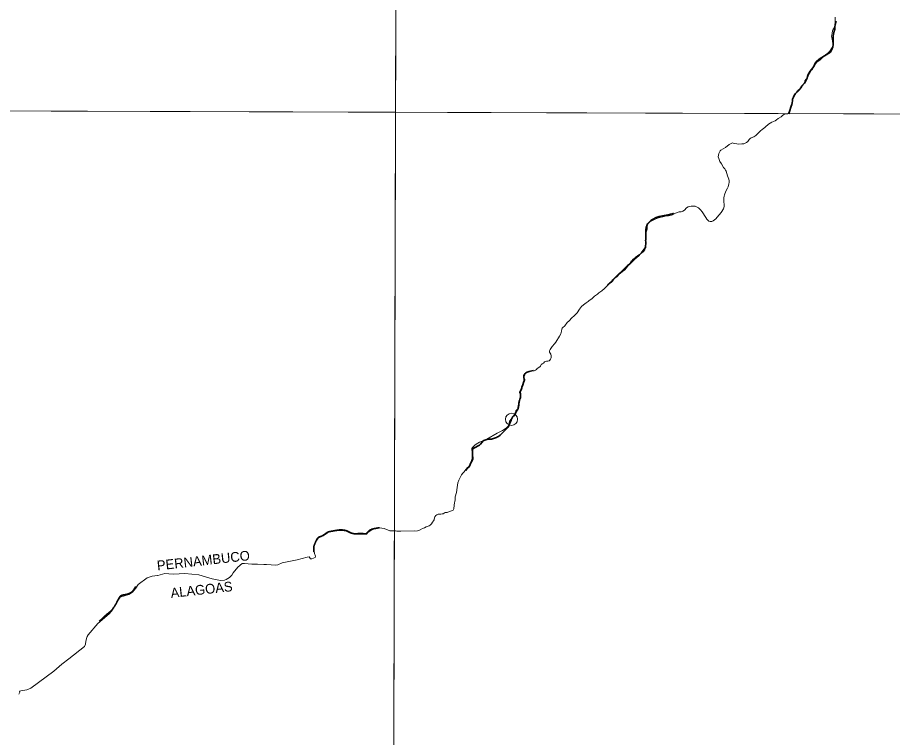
# Model space of a CAD drawing. Extents: x -1643653 to 4543381, y 1624270 to 13878484.
# Drawn here: x 582541 to 589726, y 8915895 to 8921805 of the extents above; entities that cross this region are included whole.
import ezdxf
from ezdxf.enums import TextEntityAlignment as Align

# ---------------------------------------------------------------- set-up
doc = ezdxf.new("R2010")
doc.units = 0
doc.header["$LTSCALE"] = 200
doc.header["$PDMODE"] = 32
doc.header["$PDSIZE"] = 100
doc.linetypes.add('LONG_DASH_SHORT_DASH', pattern=[9.9, 6, -1.2, 1.5, -1.2])
doc.layers.add('6', color=7, linetype='Continuous', lineweight=13)
doc.layers.add('60', color=7, linetype='Continuous', lineweight=13)

msp = doc.modelspace()

# ---------------------------------------------------------------- linework, layer by layer
at = {"layer": '6', "linetype": 'LONG_DASH_SHORT_DASH', "lineweight": 35}
msp.add_line((585799, 8917597.9), (585799.3, 8917597.8), dxfattribs=at)
at = {"layer": '6'}
for points in [[(585656.3, 8924738.8), (585614.8, 8909969.8), (585573.6, 8896026.7)], [(589006.9, 8921286.1), (589017.7, 8921298.2), (589025.9, 8921311.4), (589032.3, 8921323.1), (589038.7, 8921335.9), (589044.8, 8921346.8), (589061.1, 8921374.5), (589062.1, 8921375.7), (589065.5, 8921376.8), (589066.3, 8921377.4), (589067.9, 8921382.3), (589080.2, 8921406.4), (589088.1, 8921416.9), (589095.6, 8921428.2), (589103, 8921436.9), (589114.8, 8921446.2), (589127.9, 8921454.3), (589138.6, 8921462.4), (589156.6, 8921481.7), (589166.2, 8921490.8), (589178.1, 8921500.6), (589191.4, 8921510), (589200.1, 8921518.9), (589210.1, 8921529.4), (589229.5, 8921558.3), (589234.5, 8921575.8), (589235.7, 8921589), (589233, 8921614.5), (589230.5, 8921626.8), (589227.1, 8921641), (589225.9, 8921651.4), (589226.5, 8921662.7), (589229.7, 8921674.9), (589234.2, 8921697.9), (589238.6, 8921709.2), (589245.8, 8921721.4), (589253.2, 8921743.4), (589255.8, 8921757.4), (589255.8, 8921769.2), (589254.4, 8921783), (589254.5, 8921808.2)], [(588894.1, 8921078.3), (588899.6, 8921098.8), (588904.2, 8921126.1), (588914.3, 8921152.8), (588920.1, 8921165.7), (588925.5, 8921176.6), (588933.3, 8921185.3), (588950, 8921200.7), (588958.1, 8921209.6), (588965.2, 8921218.7), (588971.4, 8921228.1), (588977.2, 8921237.7), (588983.2, 8921246), (588992.1, 8921255.2), (589001.3, 8921265.6), (589006.1, 8921273.9), (589006.9, 8921286.1)], [(574684.9, 8921064.7), (596639.8, 8920989.8), (607636.3, 8920937.2), (626625.7, 8920820.5)], [(588866, 8921014.8), (588889.6, 8921061.5), (588894.1, 8921078.3)], [(588655.6, 8920885.9), (588677.4, 8920901.9), (588686.9, 8920909.9), (588701.1, 8920923.5), (588708.3, 8920929.1), (588735.8, 8920945.1), (588763.3, 8920958.1), (588772.3, 8920964.5), (588787.3, 8920977.1), (588811.4, 8920991.1), (588822.9, 8921000.3), (588834.6, 8921008.1), (588849.2, 8921013.6), (588866, 8921014.8)], [(588133.1, 8920242.8), (588149.7, 8920226.2), (588162.1, 8920210.6), (588192.2, 8920163.2), (588200.8, 8920151.2), (588210.3, 8920141), (588218.2, 8920134.2), (588229.5, 8920131.2), (588239.4, 8920130.6), (588242.6, 8920131.2), (588252.2, 8920136.2), (588263.6, 8920144.6), (588274.1, 8920153.8), (588286.8, 8920167.4), (588317.7, 8920204.6), (588338.9, 8920234.8), (588341.5, 8920240.4), (588344.1, 8920258), (588343.1, 8920273.4), (588340.8, 8920288.6), (588341.3, 8920325.6), (588343.4, 8920340), (588346, 8920349.4), (588356.8, 8920379.2), (588371.2, 8920405), (588375.2, 8920414.2), (588383.2, 8920440), (588384.8, 8920451.4), (588384.9, 8920464.6), (588382.6, 8920479), (588371.7, 8920504.6), (588359.6, 8920544.4), (588355, 8920553.2), (588348.1, 8920563.6), (588339.4, 8920574.6), (588322.3, 8920605), (588308.9, 8920623.2), (588298.6, 8920647.4), (588295.4, 8920660.6), (588295.9, 8920674.4), (588299.2, 8920688.8), (588303.9, 8920701), (588310.3, 8920711), (588316.9, 8920717), (588354.3, 8920738), (588383.7, 8920762), (588395.1, 8920768.6), (588407.3, 8920773.8), (588413, 8920775.2), (588418.4, 8920774.8), (588460.6, 8920766.8), (588487.3, 8920768.8), (588503.7, 8920768.2), (588522.2, 8920775.8), (588526.8, 8920778.8), (588537.4, 8920788.2), (588548.5, 8920803.2), (588555.8, 8920810.9), (588564.9, 8920816.8), (588587.7, 8920826.9), (588603.8, 8920836.1), (588610.7, 8920843.9), (588624, 8920855.9), (588641.9, 8920874.5), (588655.5, 8920886.1)], [(587691.5, 8919899.2), (587695.6, 8919912), (587699.2, 8919964.2), (587697.5, 8919992.4), (587697.6, 8920004.6), (587700.8, 8920020), (587703.5, 8920044.2), (587710.4, 8920069), (587712.5, 8920094.4), (587714.5, 8920104.2), (587717.9, 8920111), (587723, 8920118), (587730.8, 8920125.6), (587748.4, 8920136.4), (587759.7, 8920142.4), (587778.2, 8920150.6), (587804, 8920160), (587849.8, 8920172.2), (587870.3, 8920176.6), (587885.6, 8920178.2), (587910.3, 8920183.8), (587917, 8920186.6), (587930.3, 8920193.8), (587965.5, 8920207.4), (587974.1, 8920208.8), (587989.3, 8920209.2), (587999.8, 8920211.8), (588005.2, 8920214.8), (588016.8, 8920224), (588035.3, 8920241.8), (588046.8, 8920250.6), (588055.4, 8920254.4), (588071.6, 8920256.6), (588094, 8920257.2), (588104.9, 8920255.8), (588121.9, 8920249.6), (588133.1, 8920242.8)], [(586916.9, 8918999.4), (586921.8, 8919011.7), (586923.2, 8919017.8), (586923.8, 8919027.8), (586919.9, 8919040.7), (586909.9, 8919057.1), (586909, 8919064.2), (586909.4, 8919069.7), (586914.4, 8919080.4), (586932.4, 8919104.2), (586949.8, 8919125.1), (586961.5, 8919140.2), (586992.8, 8919190.2), (587002.7, 8919209.4), (587006.2, 8919218.4), (587008.9, 8919230.4), (587010.4, 8919247.4), (587012.9, 8919254.6), (587016, 8919258.6), (587035, 8919274.8), (587055.6, 8919302.4), (587072, 8919316.4), (587094, 8919340.4), (587112.3, 8919355.2), (587126.1, 8919368.8), (587137.1, 8919382), (587155.1, 8919411), (587172.6, 8919433.8), (587187.4, 8919446.2), (587211.4, 8919462), (587226.2, 8919474.8), (587234.8, 8919481.4), (587256, 8919495), (587279.1, 8919516.8), (587302.2, 8919534.6), (587313.3, 8919545), (587338.1, 8919562.4), (587360.9, 8919581.2), (587383.5, 8919602), (587399.3, 8919618), (587418.7, 8919633.8), (587431.5, 8919646.8), (587438.1, 8919658.2), (587442.8, 8919664), (587447.3, 8919667.4), (587454, 8919670.8), (587465.3, 8919679.2), (587481.8, 8919698.6), (587488.5, 8919705), (587509.1, 8919720), (587523.9, 8919732.2), (587542.4, 8919750.6), (587556.5, 8919769.4), (587562.2, 8919775.8), (587583.5, 8919793.8), (587602, 8919814.2), (587611.3, 8919821.8), (587622.8, 8919832.8), (587643.4, 8919849.8), (587655.9, 8919864), (587663.9, 8919871.6), (587678.6, 8919882), (587683.7, 8919887), (587691.5, 8919899.2), (587691.5, 8919899.2)], [(586679.6, 8918760.5), (586680.3, 8918772.5), (586692.5, 8918786.5), (586696.8, 8918798.9), (586696.9, 8918809.3), (586697.7, 8918812.7), (586699.3, 8918815.3), (586704.2, 8918820.1), (586707.7, 8918826.9), (586707.4, 8918834.5), (586702.6, 8918847.7), (586701.8, 8918857.5), (586703.1, 8918864.1), (586709.7, 8918881.3), (586721, 8918893.5), (586725.9, 8918895.7), (586766.1, 8918904.9), (586782.2, 8918905.1), (586794.3, 8918909.1), (586801.8, 8918914.7), (586808.8, 8918923.3), (586813, 8918927.3), (586824.3, 8918933.9), (586830.1, 8918938.5), (586834.8, 8918944.1), (586841.9, 8918955.9), (586845.8, 8918960.3), (586848.8, 8918962.4), (586859.7, 8918966.8), (586863.7, 8918970.4), (586869.3, 8918977.4), (586877.2, 8918981.7), (586883.6, 8918984.1), (586895.7, 8918985.2), (586905.7, 8918987.4), (586911.9, 8918992.7), (586916.9, 8918999.4)], [(586136.8, 8917879.9), (586143.9, 8917898.3), (586146.5, 8917907.1), (586150.7, 8917947.5), (586156.3, 8917986.5), (586166.2, 8918006.3), (586175.4, 8918028.7), (586186.6, 8918050.1), (586197.8, 8918063.5), (586206.1, 8918071.9), (586225, 8918098.7), (586234.8, 8918109.9), (586249.5, 8918120.5), (586256.8, 8918127.7), (586261.3, 8918135.7), (586262.8, 8918149.5), (586276.3, 8918165.5), (586281.8, 8918176.7), (586282.8, 8918182.3), (586282.8, 8918191.1), (586279.2, 8918209.5), (586279.1, 8918219.3), (586275.1, 8918241.3), (586270.8, 8918255.1), (586270.6, 8918261.3), (586271.5, 8918267.7), (586278.2, 8918274.1), (586295.8, 8918294.9), (586307.4, 8918303.7), (586335.1, 8918320.1), (586377.8, 8918336.7), (586395.1, 8918344.9), (586480.1, 8918393.5), (586505.7, 8918406.7), (586524.1, 8918414.9), (586554, 8918433.1), (586568.4, 8918447.3), (586570.6, 8918451.1), (586575.7, 8918463.9), (586578.3, 8918475.3), (586579.7, 8918491.9), (586595.5, 8918507.3), (586602.8, 8918522.3), (586607.5, 8918529.5), (586619.7, 8918540.1), (586627.3, 8918548.9), (586630.1, 8918555.5), (586632.3, 8918569.5), (586634.1, 8918575.1), (586636.7, 8918579.5), (586645.9, 8918589.1), (586648.8, 8918594.9), (586650.6, 8918604.3), (586653.5, 8918631.7), (586658.1, 8918644.7), (586665.3, 8918659.3), (586672.6, 8918692.7), (586672.6, 8918710.3), (586671.1, 8918715.7), (586665.9, 8918726.3), (586666, 8918731.5), (586668, 8918736.7), (586678.5, 8918755.1), (586678.5, 8918755.1), (586679.6, 8918760.5)], [(585824.4, 8917592.5), (585835.6, 8917593.5), (585848.5, 8917598.3), (585866.6, 8917609.5), (585883, 8917614.7), (585896.8, 8917622.9), (585921, 8917633.3), (585928.7, 8917638.5), (585940.3, 8917649.7), (585947.5, 8917662.7), (585957.1, 8917673.5), (585961.2, 8917682.5), (585965.9, 8917699.7), (585968.9, 8917706.9), (585976, 8917717.1), (585984.1, 8917723.9), (585988.6, 8917725.7), (585994.5, 8917727.1), (586017.6, 8917728.5), (586028.1, 8917729.9), (586035.3, 8917731.9), (586054, 8917741.3), (586060.6, 8917742.5), (586070, 8917742.7), (586088.9, 8917750.3), (586104.1, 8917754.3), (586112.5, 8917757.7), (586118, 8917762.1), (586120.7, 8917766.5), (586122.9, 8917773.1), (586126.9, 8917800.7), (586130.7, 8917821.1), (586131.4, 8917832.3), (586133.7, 8917846.3), (586134.3, 8917870.5), (586136.8, 8917879.9)], [(584946, 8917362.1), (584956.7, 8917362.1), (584984.5, 8917371.3), (584987.1, 8917382.3), (584980.7, 8917404.5), (584974.8, 8917448.6), (584983.7, 8917481.7), (584998.1, 8917514.8), (585010.1, 8917531), (585049.8, 8917550.4), (585085.7, 8917573.9), (585106.9, 8917582), (585162.1, 8917591.8), (585206.3, 8917594.7), (585224.1, 8917592.2)], [(585224.1, 8917592.2), (585233.4, 8917590.9), (585273.5, 8917573.1), (585302.3, 8917565), (585331.2, 8917562.9), (585406.5, 8917564.6)], [(585406.5, 8917564.6), (585417.5, 8917578), (585441.3, 8917595.2), (585463.8, 8917604.5), (585514.8, 8917615.6), (585533.1, 8917613.4)], [(585533.1, 8917613.4), (585551.5, 8917611.2), (585597.6, 8917591.8)], [(585597.6, 8917591.8), (585645.8, 8917591.3), (585655.1, 8917588.7), (585668.4, 8917587.5), (585687.5, 8917587.3), (585824.4, 8917592.5)], [(584562.5, 8917316.2), (584584.8, 8917316), (584661, 8917309.7), (584679.6, 8917312.2), (584715.2, 8917328.8), (584836.7, 8917352.1), (584920.8, 8917375.9), (584935.7, 8917377.6), (584946, 8917362.1)], [(584289.7, 8917215.3), (584302.2, 8917227.5), (584311.2, 8917245.5), (584349.8, 8917291.8), (584386.3, 8917322.1), (584405.1, 8917324.1), (584466.3, 8917316.9), (584511.8, 8917316.6), (584562.5, 8917316.2)], [(583605.6, 8917205.9), (583606.2, 8917206.4), (583647.1, 8917217.9), (583691.7, 8917225.1), (583694.7, 8917225.9)], [(583694.7, 8917225.9), (583751.3, 8917239.9), (583784.8, 8917238.2)], [(583784.8, 8917238.2), (583823, 8917236.2), (583913.9, 8917240), (584030.3, 8917229.4), (584139.1, 8917197.5), (584207.1, 8917184.8), (584241.1, 8917186), (584254.7, 8917190.7), (584281.9, 8917207.8), (584289.7, 8917215.3)], [(583497.2, 8917101.5), (583513.7, 8917119.7), (583530.7, 8917150.3), (583605.6, 8917205.9)], [(583374.4, 8917029.3), (583384.1, 8917046.7), (583454.1, 8917069.1), (583484.8, 8917087.9), (583497.2, 8917101.5)], [(583110.2, 8916714.5), (583112.9, 8916723.3), (583122.7, 8916738.7), (583200.6, 8916830.8), (583293.7, 8916911.2), (583311.9, 8916931.1), (583355.3, 8916994.9), (583374.4, 8917029.3)], [(583090.8, 8916642.8), (583100.4, 8916661.6), (583101.2, 8916686.4), (583110.2, 8916714.5)], [(582550.9, 8916251), (582561.6, 8916267.1), (582557.7, 8916274.2), (582569.7, 8916279), (582618.1, 8916284.9), (582650.7, 8916300), (582838.2, 8916439.2), (582906.1, 8916497.3), (582963.8, 8916539.2), (583090.8, 8916642.8)]]:
    msp.add_lwpolyline(points, dxfattribs=at)
for points in [[(585656.3, 8924738.8), (596655.5, 8924715.8), (596639.8, 8920989.8), (585645.8, 8921027.3)], [(585645.8, 8921027.3), (574684.9, 8921064.7), (574653.9, 8910009.3), (585614.8, 8909969.8)]]:
    msp.add_lwpolyline(points, close=True, dxfattribs=at)
at = {"layer": '6', "linetype": 'LONG_DASH_SHORT_DASH', "lineweight": 35}
for points in [[(589262.4, 8921776.3), (589254.8, 8921747.1), (589251.8, 8921726), (589251.4, 8921710.4), (589247.4, 8921693.8), (589239.5, 8921655.1), (589239.6, 8921610.4), (589237.7, 8921580.3), (589235.3, 8921563.7), (589231.3, 8921549.6), (589215.3, 8921521.4), (589132.6, 8921468.3), (589120.5, 8921461.2), (589098, 8921441), (589090.5, 8921429.4), (589084, 8921417.3), (589078.5, 8921402.8), (589050.5, 8921365.4), (589040.5, 8921350.3), (589033.5, 8921337.8), (589029, 8921322.2), (589025.5, 8921307.1), (589017.5, 8921291.5), (589010.5, 8921279.4), (589002, 8921266.3), (588982.5, 8921240.6), (588974, 8921227.5), (588964.5, 8921217.4), (588950.5, 8921205.3), (588938.9, 8921193.2), (588929.9, 8921182.6), (588918.9, 8921166.4), (588912.4, 8921152.3), (588906, 8921134.7), (588905.5, 8921121.2), (588902, 8921105.6), (588899.1, 8921090), (588894.1, 8921076.4), (588881.2, 8921032.6), (588876.7, 8921019.1), (588873.6, 8921014.8)], [(587701.6, 8920064.6), (587703.2, 8920080.8), (587707.8, 8920095.9), (587711, 8920103.7), (587715.3, 8920111.1), (587726.9, 8920123.9), (587733.5, 8920129.9), (587738.1, 8920135.1), (587744.4, 8920140.8), (587750.3, 8920144.2), (587771.1, 8920154.8), (587778.3, 8920159.7), (587792.9, 8920165.5), (587808.5, 8920171.2), (587837.1, 8920177.3), (587851.6, 8920180.9), (587880.5, 8920185.8), (587895.1, 8920188.6), (587902.5, 8920190.3), (587916.5, 8920192.8), (587924.1, 8920195.4), (587926.9, 8920195.9)], [(587384.3, 8919609.4), (587392.8, 8919616.3), (587405.5, 8919627.7), (587412.1, 8919632.4), (587417.9, 8919638.4), (587424.8, 8919644.2), (587430.4, 8919650.8), (587441.5, 8919662), (587541.8, 8919762.6), (587551.1, 8919770.1), (587557.9, 8919776), (587563.2, 8919781.1), (587576.3, 8919795.3), (587583.5, 8919804.2), (587591.3, 8919812.9), (587606.1, 8919826.6), (587612.5, 8919831.4), (587618.5, 8919836.6), (587624.4, 8919840.8), (587631.5, 8919846.6), (587642.7, 8919854.2), (587649.1, 8919858.2), (587655, 8919862.8), (587659.9, 8919868.4), (587664.8, 8919874.6), (587695.6, 8919913.3), (587697.2, 8919915.7), (587699.1, 8919965.1), (587698.6, 8919973.8), (587699.4, 8919981), (587699.3, 8919988.3), (587699.9, 8919996), (587699.5, 8920003.7), (587699.7, 8920011.4), (587699.3, 8920019.1), (587700.3, 8920027), (587701.3, 8920041), (587701.6, 8920049.7), (587701.4, 8920057.6), (587701.6, 8920064.6)], [(586698.2, 8918860.5), (586699.5, 8918868.4), (586701.6, 8918872.3), (586709.1, 8918881.7), (586716.2, 8918889), (586725.8, 8918894.1), (586735.2, 8918897.5), (586743.7, 8918899.7), (586775.5, 8918907)], [(586597.6, 8918506.7), (586605.9, 8918523.4), (586611.9, 8918529.9), (586617.3, 8918534), (586622.3, 8918538.9), (586623.4, 8918540.9), (586626.4, 8918548.8), (586631.3, 8918557.1), (586634.3, 8918565.1), (586637.8, 8918573), (586643.9, 8918581.7), (586648.8, 8918589.4), (586652.3, 8918595.6), (586654.7, 8918605.5), (586654.8, 8918613.8), (586656.7, 8918622.1), (586657.8, 8918638.2), (586659.7, 8918646.3), (586661, 8918654.2), (586663.5, 8918662.4), (586666.6, 8918670.9), (586668.9, 8918678.8), (586672.1, 8918687.1), (586672.3, 8918702.8), (586672, 8918712), (586671, 8918719.4), (586667.1, 8918727.6), (586666.9, 8918728.6), (586672.8, 8918742), (586679.1, 8918756), (586680.9, 8918764.7), (586683.4, 8918772.6), (586688.5, 8918781.8), (586690.3, 8918790.4), (586695.8, 8918807.9), (586701.3, 8918821.4), (586701.6, 8918825.4), (586701.4, 8918834.4), (586699.1, 8918851.1), (586698.2, 8918860.5)], [(586513.5, 8918384.7), (586547.2, 8918421.3), (586562.5, 8918435.2), (586568.8, 8918442), (586573.9, 8918450.3), (586577.2, 8918457.8), (586580, 8918465.9), (586583.2, 8918474), (586594.1, 8918498), (586597.6, 8918506.7)], [(586222.6, 8918087.9), (586223.9, 8918090.1), (586228.4, 8918096.1), (586236.5, 8918103.6), (586243.8, 8918110.9), (586250.2, 8918118.5), (586254.6, 8918126.4), (586260.8, 8918142.7), (586268.8, 8918158.2), (586272.8, 8918166.7), (586277.2, 8918183.1), (586278.1, 8918191.2), (586277.5, 8918199.5), (586276, 8918207.8), (586276, 8918223.7), (586276.6, 8918240), (586275.8, 8918254), (586276.7, 8918256.6), (586280.2, 8918263.9), (586287.4, 8918268.9), (586293.9, 8918272.7), (586327.8, 8918291.2), (586334.7, 8918295.4), (586343.5, 8918302.7), (586357.8, 8918319.5), (586363.1, 8918326.4), (586369.2, 8918332), (586377.3, 8918336.3), (586385.6, 8918339.6), (586393.6, 8918341.5), (586401.5, 8918342.9), (586433.8, 8918344.2), (586442.3, 8918345.8), (586450.6, 8918348.2), (586466.5, 8918353.8), (586474.8, 8918357.3), (586483.3, 8918361.6), (586490.3, 8918366.2), (586504.2, 8918377.5), (586513.5, 8918384.7)]]:
    msp.add_lwpolyline(points, dxfattribs=at)
for points in [[(584975.9, 8917417.5), (584975.5, 8917419.7), (584973.4, 8917450.5), (584981.3, 8917482.8), (584997.8, 8917518.6), (585007.8, 8917534.4), (585031.4, 8917545.1), (585065.1, 8917565.2), (585093, 8917581.7), (585131, 8917589.6), (585175.4, 8917597.4), (585208.4, 8917598.2), (585232.7, 8917594.6), (585252.1, 8917588.1), (585282.1, 8917573.1), (585320.8, 8917565.9)], [(585320.8, 8917565.9), (585379.6, 8917568.1), (585403.9, 8917567.3), (585406.1, 8917568.8), (585417.5, 8917582.4), (585451.2, 8917604.6), (585489.2, 8917612.5), (585512.1, 8917617.4)], [(583212.7, 8916848.6), (583254.2, 8916889.7), (583303.2, 8916930.2), (583370.6, 8917031.5), (583385.8, 8917055.2), (583431.4, 8917068.7), (583482, 8917092.3), (583511.3, 8917134.2)]]:
    msp.add_spline(points, degree=3, dxfattribs=at)
at = {"layer": '6'}
msp.add_point((586597.6, 8918506.7), dxfattribs=at)
at = {"layer": '60', "lineweight": 25}
msp.add_spline([(814781, 9009175.5), (814787.2, 9009173.4), (814796.9, 9009173.4), (814799.4, 9009172.4), (814805.1, 9009174.5), (814805.6, 9009176.5), (814811.7, 9009179.5), (814811.7, 9009179.5), (814801.5, 9009181), (814790.7, 9009181.5), (814784.1, 9009183.1), (814777.4, 9009185.1), (814778.4, 9009175.5)], degree=3, dxfattribs=at)

# ---------------------------------------------------------------- texts
at = {"layer": '6'}
for s, p in [('PERNAMBUCO', (584071.7, 8917308.3)), ('ALAGOAS', (584056.6, 8917068.5))]:
    msp.add_text(s, height=80, rotation=6.379, dxfattribs=at).set_placement(p, align=Align.CENTER)

doc.saveas('drawing.dxf')
